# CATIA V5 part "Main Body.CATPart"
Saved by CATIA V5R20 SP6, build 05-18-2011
Part number: Main Body
Bounding box of the stored display mesh (mm): x 0 to 30, y -30.009 to 69, z -34 to 36.997
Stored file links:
  E:\#01 CATIA Lecture Materials\#06 DMU\#03 DMU Page01 KIN EX03\Main Body.CATPart
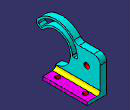
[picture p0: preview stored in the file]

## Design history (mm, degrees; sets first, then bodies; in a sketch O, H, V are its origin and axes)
Set1 "Reference Data"
  Point1 "Center Point": (0, 0, 0)
  Plane1 "Plane.1(Y Dir=69mm)": type Offset, RefPlane zx-plane, Offset 69
  Plane2 "Plane.2(Z Dir=-34mm": type Offset, RefPlane xy-plane, Offset 34, reversed
Body1 (main body)
  Body2 "Main Body"
    Sketch1 on yz-plane, origin (0, 0, 0), H (0, 1, 0), V (0, 0, 1)
      arc A1 centre (0, 0) radius 23 from (0, -23) to (-20.4003, 10.6221) ccw
      construction circle A2 centre (0, 0) radius 30
      arc A3 centre (0, 0) radius 37 from (31.1288, 20) to (-31.9296, 18.695) ccw
      construction line L1 (0, 0) -> (-30.3086, 21.2223)
      point P1 (-30.3086, 21.2223)
      construction line L2 (0, 0) -> (37, 0)
      point P2 (37, 0)
      line L3 (-20.4003, 10.6221) -> (-31.9296, 18.695)
      point P3 (-1.7207, -2.4575)
      point P4 (-32.0294, 18.7649)
      construction line L4 (0, 0) -> (-1.7207, -2.4575)
      construction line L5 (-30.3086, 21.2223) -> (-32.0294, 18.7649)
      line L6 (31.1288, 20) -> (69, 20)
      line L7 (69, 20) -> (69, -34)
      line L8 (69, -34) -> (0, -34)
      point P7 (0, -34)
      line L9 (0, -34) -> (0, -23)
      arc A4 centre (0, 0) radius 34 from (34, 0) to (-27.8512, 19.5016) ccw
      arc A5 centre (0, 0) radius 26 from (26, 0) to (-21.298, 14.913) ccw
      line L10 (26, 0) -> (34, 0)
      point P12 (26, 0)
      line L11 (-21.298, 14.913) -> (-27.8512, 19.5016)
      point P13 (-21.298, 14.913)
      reference intersected line E1 through (69, 0) direction (0, 1) from Plane1
      reference intersected line E2 through (0, -34) direction (-1, 0) from Plane2
      radius A1 = 23
      radius A2 = 30
      radius A3 = 37
      angle V L1 = 55
      distance L1 L3 = 3
      distance L8 L6 = 54
      distance A2 A4 = 4
      distance A2 A5 = 4
      coincidence: P1 A3, P2 A3, P7 V, P3 L3, P4 L3, P12 A5, P12 L2, P13 A5, P13 L1, P13 L11, P12 L10, L7 E1, L8 E2
      horizontal: L2 H, L6 H, L8 H, L10 H
      perpendicularity: L4 L1, L4 L3, L5 L1, L5 L3
      vertical: L7 V, L9 V
      concentricity: A2 A4, A2 A5
      parallelism: L11 L1
    Pad1: profile Sketch1, direction (1, 0, 0), length 10
    Fillet1: radius 10, on edge [face of Pad1 from Sketch1.L6 | face of Pad1 from Sketch1.L7]; edge [face of Pad1 from Sketch1.A3 | face of Pad1 from Sketch1.L6]
    Fillet2: radius 2, on edge [face of Pad1 from Sketch1.A4 | face of Pad1 from Sketch1.L11]; edge [face of Pad1 from Sketch1.L11 | face of Pad1 from Sketch1.A5]; edge [face of Pad1 from Sketch1.A5 | face of Pad1 from Sketch1.L10]; edge [face of Pad1 from Sketch1.L10 | face of Pad1 from Sketch1.A4]
    Fillet3: radius 5, on edge [face of Pad1 from Sketch1.L3 | face of Pad1 from Sketch1.A3]; edge [face of Pad1 from Sketch1.A1 | face of Pad1 from Sketch1.L3]
  Assemble1: tool Body2
  Body3 "Base Body"
    Sketch2 on yz-plane, origin (0, 0, 0), H (0, 1, 0), V (0, 0, 1)
      point P1 (0, -29)
      line L1 (0, -29) -> (69, -29)
      line L2 (69, -29) -> (69, -34)
      line L3 (69, -34) -> (0, -34)
      line L4 (0, -34) -> (0, -29)
      reference intersected line E1 through (69, 0) direction (0, 1) from Plane1
      reference intersected line E2 through (0, -34) direction (-1, 0) from Plane2
      distance L3 L1 = 5
      coincidence: P1 V, L2 E1, L3 E2
      horizontal: L1 H, L3 H
      vertical: L2 V, L4 V
    Pad2: profile Sketch2, direction (1, 0, 0), length 30
  Assemble2: tool Body3
  Fillet4: radius 5, on edge [end face of Pad1 | face of Pad2 from Sketch2.L1]
  Body4 "Hole Body"
    Body5 "Hole Body(D8)"
      Sketch3 on yz-plane, origin (0, 0, 0), H (0, 1, 0), V (0, 0, 1)
        circle A1 centre (48, -1) radius 4
        point P1 (48, -1)
        reference intersected line E1 through (0, -34) direction (-1, 0) from Plane2
        distance P1 V = 48
        distance E1 P1 = 33
        radius A1 = 4
      Pad3: profile Sketch3, direction (1, 0, 0), length 30
    Assemble3: tool Body5
    Body6 "Hole Body(D7)"
      Sketch4 on Plane2, origin (0, 0, -34), H (0, 1, 0), V (-1, 0, 0)
        circle A1 centre (13, -20) radius 3.5
        point P1 (13, -20)
        distance V P1 = 13
        distance H P1 = 20
        radius A1 = 3.5
      Pad4: profile Sketch4, direction (0, 0, 1), length 30
      RectPattern1: of the body so far, direction 1 instances 2, spacing 43, along edge [face of Pad2 from Sketch2.L1 | end face of Pad2] reversed
    Assemble4: tool Body6
  Remove1: tool Body4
